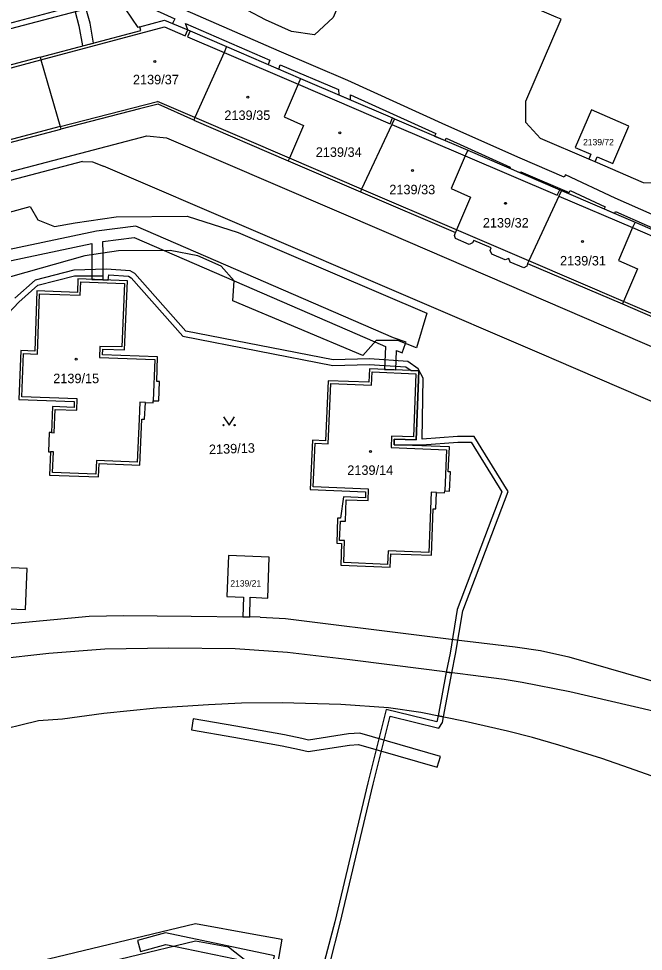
# Model space of a CAD drawing. Extents: x -756746 to -753363, y -1166406 to -1161727.
# Drawn here: x -756319.3 to -756207.5, y -1164267.8 to -1164100.9 of the extents above; entities that cross this region are included whole.
import ezdxf

# ---------------------------------------------------------------- set-up
doc = ezdxf.new("R2010")
doc.units = 0
for name, color, linetype in [('Hranice parcel', 7, 'Continuous'), ('Parcelní čísla', 7, 'Continuous'), ('Vnitřní kresba', 7, 'Continuous'), ('Věcná břemena k části', 7, 'Continuous'), ('Značky budov', 7, 'Continuous'), ('Značky kultur', 7, 'Continuous')]:
    doc.layers.add(name, color=color, linetype=linetype)

msp = doc.modelspace()

# ---------------------------------------------------------------- linework, layer by layer
at = {"layer": 'Hranice parcel'}
for p, q in [((-756315.45, -1164107.81), (-756297.46, -1164103.08)), ((-756297.46, -1164103.08), (-756297.61, -1164102.39)), ((-756282.1, -1164105.94), (-756268.86, -1164111.63)), ((-756287.76, -1164118.62), (-756287.99, -1164119.11)), ((-756287.99, -1164119.11), (-756271.06, -1164126.38)), ((-756252.09, -1164118.84), (-756238.94, -1164124.5)), ((-756271.06, -1164126.38), (-756258.17, -1164131.91)), ((-756216.14, -1164126.58), (-756217.29, -1164126.09)), ((-756257.94, -1164131.42), (-756258.17, -1164131.91)), ((-756258.17, -1164131.91), (-756241.17, -1164139.21)), ((-756222.17, -1164131.71), (-756209, -1164137.37)), ((-756228.04, -1164144.25), (-756228.27, -1164144.74)), ((-756228.27, -1164144.74), (-756211.29, -1164151.98)), ((-756211.29, -1164151.98), (-756198, -1164157.69))]:
    msp.add_line(p, q, dxfattribs=at)
for points in [[(-756223.11, -1164100.67), (-756256.77, -1164086.19), (-756263.02, -1164100.73), (-756266.38, -1164103.84), (-756270.5, -1164103.24), (-756275.14, -1164101.13), (-756278.31, -1164099.51)], [(-756297.61, -1164102.39), (-756297.92, -1164102.53), (-756300.21, -1164099.16), (-756304.16, -1164098.42), (-756363.79, -1164114.05)], [(-756297.61, -1164102.39), (-756293.24, -1164101.21), (-756289.04, -1164102.96), (-756288.64, -1164103.13), (-756282.1, -1164105.94)], [(-756217.29, -1164126.09), (-756225.92, -1164122.38), (-756228.59, -1164119.53), (-756228.58, -1164115.72), (-756222.26, -1164101.04), (-756223.11, -1164100.67)], [(-756282.1, -1164105.94), (-756282.52, -1164107.01), (-756287.76, -1164118.62)], [(-756315.45, -1164107.81), (-756330.14, -1164111.72), (-756330.01, -1164112.2), (-756331.19, -1164112.52), (-756331.31, -1164112.04), (-756353.66, -1164117.9)], [(-756315.45, -1164107.81), (-756315.31, -1164108.3), (-756311.9, -1164120.25), (-756311.76, -1164120.73)], [(-756268.86, -1164111.63), (-756269.29, -1164112.69), (-756271.79, -1164118.53)], [(-756268.86, -1164111.63), (-756252.4, -1164118.71), (-756252.09, -1164118.84)], [(-756287.99, -1164119.11), (-756294.32, -1164116.27), (-756297.69, -1164117.07), (-756311.76, -1164120.73)], [(-756216.14, -1164126.58), (-756215.78, -1164125.69), (-756213.01, -1164126.87), (-756210.12, -1164120.16), (-756216.84, -1164117.28), (-756219.73, -1164124.01), (-756216.92, -1164125.21), (-756217.29, -1164126.09)], [(-756271.79, -1164118.53), (-756268.34, -1164120.05), (-756270.85, -1164125.88), (-756271.06, -1164126.38)], [(-756252.09, -1164118.84), (-756252.52, -1164119.88), (-756257.94, -1164131.42)], [(-756351.41, -1164126.3), (-756341.53, -1164123.74), (-756340.35, -1164128.24), (-756329.27, -1164125.33), (-756311.76, -1164120.73)], [(-756357.48, -1164137.98), (-756334.62, -1164131.93), (-756296.39, -1164121.91), (-756292.85, -1164122.26), (-756253.11, -1164139.34), (-756186.55, -1164167.99), (-756184.92, -1164172.77), (-756175.62, -1164217.3), (-756144.99, -1164245.44)], [(-756238.94, -1164124.5), (-756239.42, -1164125.48), (-756241.91, -1164131.34)], [(-756238.94, -1164124.5), (-756222.48, -1164131.57), (-756222.17, -1164131.71)], [(-756151.7, -1164169.02), (-756152.31, -1164166.49), (-756154.34, -1164160.57), (-756160.31, -1164152.33), (-756162.91, -1164150.21), (-756165.16, -1164148.15), (-756166.9, -1164145.3), (-756166.68, -1164142.43), (-756178.83, -1164137.13), (-756177.37, -1164133.73), (-756187.3, -1164129.49), (-756188.76, -1164132.89), (-756200.84, -1164127.71), (-756203.83, -1164130.35), (-756207.49, -1164130.3), (-756216.14, -1164126.58)], [(-756241.91, -1164131.34), (-756238.45, -1164132.88), (-756240.95, -1164138.71), (-756241.17, -1164139.21)], [(-756222.17, -1164131.71), (-756222.64, -1164132.68), (-756228.04, -1164144.25)], [(-756333.38, -1164138.94), (-756317.27, -1164134.53), (-756315.86, -1164136.94), (-756312.9, -1164138.13), (-756309.19, -1164137.48), (-756301.87, -1164136.4), (-756289.18, -1164136.27), (-756280.04, -1164139.23), (-756246.3, -1164153.62), (-756248.15, -1164159.84), (-756251.44, -1164158.53), (-756255.37, -1164158.5), (-756257.72, -1164161.2), (-756280.98, -1164151.45), (-756280.77, -1164147.87), (-756283.08, -1164145.21), (-756287.27, -1164143.4), (-756292.17, -1164142.41), (-756301.44, -1164142.47), (-756307.47, -1164143.36), (-756320.78, -1164147.12)], [(-756209, -1164137.37), (-756209.47, -1164138.33), (-756211.99, -1164144.23)], [(-756209, -1164137.37), (-756192.55, -1164144.44), (-756192.25, -1164144.57)], [(-756228.27, -1164144.74), (-756228.36, -1164145.23), (-756228.92, -1164145.53), (-756231.39, -1164144.5), (-756231.59, -1164143.85), (-756232.24, -1164144.11), (-756234.66, -1164143.07), (-756234.93, -1164142.4), (-756234.78, -1164141.95), (-756237.89, -1164140.62), (-756238.08, -1164141.06), (-756238.73, -1164141.33), (-756241.13, -1164140.29), (-756241.34, -1164139.76), (-756241.17, -1164139.21)], [(-756211.99, -1164144.23), (-756208.59, -1164145.69), (-756211.1, -1164151.52), (-756211.29, -1164151.98)], [(-756295.23, -1164169.31), (-756294.23, -1164169.34), (-756294.11, -1164165.89), (-756294.61, -1164165.87), (-756294.45, -1164161.46), (-756304.31, -1164161.11), (-756304.27, -1164160.09), (-756300.34, -1164160.2), (-756299.84, -1164147.87), (-756308.69, -1164147.51), (-756308.78, -1164149.92), (-756316.03, -1164149.65), (-756316.44, -1164160.43), (-756318.89, -1164160.33), (-756319.25, -1164169.09), (-756309.35, -1164169.46), (-756309.39, -1164170.49), (-756313.27, -1164170.34), (-756313.45, -1164175.01), (-756313.82, -1164174.99), (-756313.96, -1164178.42), (-756313.59, -1164178.43), (-756313.76, -1164182.64), (-756305, -1164182.94), (-756304.92, -1164180.53), (-756297.62, -1164180.84), (-756297.27, -1164172.6), (-756296.77, -1164172.62), (-756296.64, -1164169.62)], [(-756243.04, -1164185.43), (-756242.24, -1164185.47), (-756242.07, -1164182.02), (-756242.45, -1164182), (-756242.25, -1164177.57), (-756252.15, -1164177.18), (-756252.11, -1164176.15), (-756248.2, -1164176.32), (-756247.69, -1164163.97), (-756256.55, -1164163.6), (-756256.66, -1164166.01), (-756263.95, -1164165.72), (-756264.39, -1164176.48), (-756266.76, -1164176.38), (-756267.13, -1164185.17), (-756257.22, -1164185.61), (-756257.27, -1164186.65), (-756261.17, -1164186.49), (-756261.72, -1164190.32), (-756262.23, -1164190.3), (-756262.4, -1164194.77), (-756261.52, -1164194.82), (-756261.68, -1164198.7), (-756252.83, -1164199.11), (-756252.73, -1164196.71), (-756245.42, -1164196.96), (-756245.14, -1164188.65), (-756244.64, -1164188.66), (-756244.52, -1164185.71)], [(-756296.64, -1164169.62), (-756295.24, -1164169.67), (-756295.23, -1164169.31)], [(-756244.52, -1164185.71), (-756243.1, -1164185.76), (-756243.04, -1164185.43)], [(-756282.07, -1164204.34), (-756279.05, -1164204.45), (-756279.17, -1164207.96), (-756277.94, -1164207.97), (-756277.91, -1164204.42), (-756274.75, -1164204.62), (-756274.46, -1164197.29), (-756281.77, -1164196.99), (-756282.07, -1164204.34)], [(-756321.16, -1164206.56), (-756318.1, -1164206.67), (-756317.78, -1164199.33), (-756325.13, -1164199.01), (-756325.41, -1164206.39), (-756322.39, -1164206.51), (-756322.5, -1164209.38), (-756321.24, -1164209.24), (-756321.16, -1164206.56)], [(-756148.36, -1164249.07), (-756153.72, -1164245.95), (-756161.21, -1164238.9), (-756170.46, -1164234.4), (-756177.88, -1164231.27), (-756185.24, -1164228.27), (-756190.49, -1164227.79), (-756205.8, -1164224.82), (-756220.7, -1164221.36), (-756229.23, -1164219.69), (-756232.44, -1164219.17), (-756246.35, -1164217.38), (-756260.03, -1164215.68), (-756271.23, -1164214.36), (-756280.57, -1164213.67), (-756292.45, -1164213.57), (-756303.87, -1164213.75), (-756313.9, -1164214.51), (-756323.57, -1164215.6), (-756333.21, -1164216.94), (-756339.63, -1164217.97), (-756353.1, -1164221.07)], [(-756205.15, -1164236.76), (-756210, -1164235.05), (-756214.99, -1164233.33), (-756222.65, -1164230.91), (-756227.38, -1164229.56), (-756231.87, -1164228.45), (-756239.41, -1164226.68), (-756247.36, -1164225.07), (-756253.15, -1164224.26), (-756261.68, -1164223.66), (-756272.14, -1164223.37), (-756279.45, -1164223.39), (-756285.31, -1164223.72), (-756294.64, -1164224.32), (-756304.04, -1164225.26), (-756311.44, -1164226.29), (-756315.76, -1164226.6), (-756324.56, -1164228.71)]]:
    msp.add_lwpolyline(points, dxfattribs=at)
at = {"layer": 'Vnitřní kresba'}
for p, q in [((-756315.31, -1164108.3), (-756293.22, -1164102.43)), ((-756293.22, -1164102.43), (-756289.49, -1164104.03)), ((-756289.49, -1164104.03), (-756289.04, -1164102.96)), ((-756288.64, -1164103.13), (-756289.08, -1164104.2)), ((-756289.08, -1164104.2), (-756282.52, -1164107.01)), ((-756282.52, -1164107.01), (-756269.29, -1164112.69)), ((-756329.32, -1164112.02), (-756315.31, -1164108.3)), ((-756269.29, -1164112.69), (-756252.82, -1164119.75)), ((-756311.9, -1164120.25), (-756294.45, -1164115.75)), ((-756287.76, -1164118.62), (-756294.45, -1164115.75)), ((-756270.85, -1164125.88), (-756287.76, -1164118.62)), ((-756252.82, -1164119.75), (-756252.4, -1164118.71)), ((-756311.9, -1164120.25), (-756329.4, -1164124.85)), ((-756252.52, -1164119.88), (-756239.42, -1164125.48)), ((-756307.87, -1164126.5), (-756357.09, -1164139.42)), ((-756307.87, -1164126.5), (-756306.11, -1164126.56)), ((-756257.94, -1164131.42), (-756270.85, -1164125.88)), ((-756239.42, -1164125.48), (-756222.96, -1164132.54)), ((-756306.11, -1164126.56), (-756304.1, -1164127.31)), ((-756224.87, -1164161.33), (-756304.1, -1164127.31)), ((-756240.95, -1164138.71), (-756257.94, -1164131.42)), ((-756222.96, -1164132.54), (-756222.48, -1164131.57)), ((-756222.64, -1164132.68), (-756209.47, -1164138.33)), ((-756228.04, -1164144.25), (-756240.95, -1164138.71)), ((-756209.47, -1164138.33), (-756193, -1164145.4)), ((-756211.1, -1164151.52), (-756228.04, -1164144.25)), ((-756308.3, -1164150.44), (-756308.21, -1164148.03)), ((-756308.21, -1164148.03), (-756300.36, -1164148.35)), ((-756300.36, -1164148.35), (-756300.82, -1164159.68)), ((-756315.96, -1164160.95), (-756315.55, -1164150.17)), ((-756315.55, -1164150.17), (-756308.3, -1164150.44)), ((-756197.8, -1164157.23), (-756211.1, -1164151.52)), ((-756304.76, -1164159.58), (-756304.83, -1164161.59)), ((-756300.82, -1164159.68), (-756304.76, -1164159.58)), ((-756318.73, -1164168.61), (-756318.41, -1164160.85)), ((-756318.41, -1164160.85), (-756315.96, -1164160.95)), ((-756223.49, -1164161.92), (-756224.87, -1164161.33)), ((-756304.83, -1164161.59), (-756294.97, -1164161.94)), ((-756294.97, -1164161.94), (-756295.23, -1164169.31)), ((-756193.75, -1164174.73), (-756223.49, -1164161.92)), ((-756256.18, -1164166.53), (-756256.07, -1164164.12)), ((-756256.07, -1164164.12), (-756248.22, -1164164.46)), ((-756248.22, -1164164.46), (-756248.69, -1164175.79)), ((-756263.91, -1164177), (-756263.47, -1164166.24)), ((-756263.47, -1164166.24), (-756256.18, -1164166.53)), ((-756308.83, -1164168.98), (-756318.73, -1164168.61)), ((-756308.91, -1164171.01), (-756308.83, -1164168.98)), ((-756297.64, -1164169.58), (-756297.77, -1164172.58)), ((-756296.64, -1164169.62), (-756297.64, -1164169.58)), ((-756312.96, -1164175.03), (-756312.79, -1164170.86)), ((-756312.79, -1164170.86), (-756308.91, -1164171.01)), ((-756297.77, -1164172.58), (-756298.1, -1164180.32)), ((-756313.45, -1164175.01), (-756312.96, -1164175.03)), ((-756252.59, -1164175.62), (-756252.68, -1164177.67)), ((-756248.69, -1164175.79), (-756252.59, -1164175.62)), ((-756266.61, -1164184.69), (-756266.28, -1164176.9)), ((-756266.28, -1164176.9), (-756263.91, -1164177)), ((-756252.68, -1164177.67), (-756242.78, -1164178.06)), ((-756242.78, -1164178.06), (-756243.04, -1164185.43)), ((-756313.09, -1164178.45), (-756313.59, -1164178.43)), ((-756313.24, -1164182.16), (-756313.09, -1164178.45)), ((-756305.4, -1164180.01), (-756305.48, -1164182.42)), ((-756298.1, -1164180.32), (-756305.4, -1164180.01)), ((-756305.48, -1164182.42), (-756313.24, -1164182.16)), ((-756256.7, -1164185.13), (-756266.61, -1164184.69)), ((-756256.79, -1164187.17), (-756256.7, -1164185.13)), ((-756245.52, -1164185.67), (-756245.91, -1164196.47)), ((-756244.52, -1164185.71), (-756245.52, -1164185.67)), ((-756260.84, -1164190.87), (-756260.69, -1164187.01)), ((-756260.69, -1164187.01), (-756256.79, -1164187.17)), ((-756261.88, -1164194.29), (-756261.74, -1164190.83)), ((-756261.74, -1164190.83), (-756260.84, -1164190.87)), ((-756260.99, -1164194.33), (-756261.88, -1164194.29)), ((-756261.15, -1164198.22), (-756260.99, -1164194.33)), ((-756253.21, -1164196.18), (-756253.32, -1164198.59)), ((-756245.91, -1164196.47), (-756253.21, -1164196.18)), ((-756253.32, -1164198.59), (-756261.15, -1164198.22)), ((-756321.24, -1164209.24), (-756306.68, -1164207.87)), ((-756306.68, -1164207.87), (-756300.49, -1164207.71)), ((-756300.49, -1164207.71), (-756294.52, -1164207.8)), ((-756294.52, -1164207.8), (-756288.43, -1164207.86)), ((-756288.43, -1164207.86), (-756279.17, -1164207.96)), ((-756276.12, -1164208), (-756277.94, -1164207.97)), ((-756276.12, -1164208), (-756271.59, -1164208.28)), ((-756271.59, -1164208.28), (-756247.63, -1164211.24)), ((-756247.63, -1164211.24), (-756240.02, -1164212.22)), ((-756240.02, -1164212.22), (-756230.45, -1164213.35)), ((-756230.45, -1164213.35), (-756225.95, -1164214.01)), ((-756225.95, -1164214.01), (-756220.88, -1164215.15)), ((-756220.88, -1164215.15), (-756189.12, -1164224.22)), ((-756316.96, -1164269.88), (-756287.66, -1164262.86)), ((-756287.66, -1164262.86), (-756277.2, -1164264.73)), ((-756277.2, -1164264.73), (-756272.2, -1164265.62)), ((-756317.43, -1164273.08), (-756287.67, -1164265.96)), ((-756287.67, -1164265.96), (-756281.76, -1164267.01)), ((-756272.2, -1164265.62), (-756273.02, -1164270.12)), ((-756281.76, -1164267.01), (-756278.66, -1164269.46))]:
    msp.add_line(p, q, dxfattribs=at)
at = {"layer": 'Věcná břemena k části'}
for points in [[(-756300.96, -1164096.54), (-756291.36, -1164100.96), (-756291.77, -1164101.82)], [(-756326.56, -1164103.26), (-756309.49, -1164098.72)], [(-756309.21, -1164099.74), (-756308.54, -1164102.21), (-756307.89, -1164105.82), (-756305.89, -1164105.3), (-756306.52, -1164101.75), (-756307.22, -1164099.22)], [(-756199.32, -1164138.89), (-756212.6, -1164133.03), (-756221.47, -1164128.9), (-756221.72, -1164129.31), (-756229.59, -1164125.91), (-756242.86, -1164119.97), (-756260.4, -1164112), (-756272.67, -1164106.76), (-756289.53, -1164099.42)], [(-756291.77, -1164101.82), (-756289.04, -1164102.96), (-756289.46, -1164101.81), (-756274.39, -1164108.37), (-756274.65, -1164109.14), (-756272.75, -1164109.96), (-756272.49, -1164109.18), (-756262.06, -1164113.64), (-756262.02, -1164114.57), (-756259.92, -1164115.48), (-756259.96, -1164114.58), (-756244.69, -1164121.51), (-756244.89, -1164121.94), (-756242.99, -1164122.76), (-756242.81, -1164122.35), (-756231.35, -1164127.49), (-756231.44, -1164127.72), (-756229.55, -1164128.53), (-756229.47, -1164128.32), (-756220.82, -1164132.05), (-756220.61, -1164131.68), (-756214.38, -1164134.58), (-756214.54, -1164134.99), (-756212.65, -1164135.8), (-756212.5, -1164135.43), (-756201.16, -1164140.44)], [(-756352.82, -1164151.04), (-756306.22, -1164141.16), (-756306.21, -1164143.17), (-756306.19, -1164147.61), (-756304.19, -1164147.69), (-756304.21, -1164142.88), (-756304.22, -1164140.81), (-756298.65, -1164140.09), (-756293.28, -1164142.42), (-756280.77, -1164147.87), (-756255.59, -1164158.75), (-756253.69, -1164159.58), (-756253.83, -1164163.71), (-756251.83, -1164163.8), (-756251.71, -1164160.34), (-756250.67, -1164160.72), (-756250.07, -1164159.08), (-756249.99, -1164158.84), (-756252.26, -1164158.02), (-756298.35, -1164138.04), (-756305.39, -1164138.95), (-756352.3, -1164148.88)], [(-756334.92, -1164168.19), (-756319.27, -1164151.66), (-756315.86, -1164148.62), (-756309.29, -1164146.93), (-756304.45, -1164146.95), (-756304.22, -1164147.04), (-756304.27, -1164147.69), (-756303.27, -1164147.73), (-756303.2, -1164146.78), (-756299.66, -1164147.03), (-756299.15, -1164147.33), (-756289.91, -1164157.78), (-756263.1, -1164163.01), (-756256.57, -1164162.81), (-756250.04, -1164163.25), (-756249.1, -1164163.91), (-756247.69, -1164163.97), (-756248.2, -1164176.32), (-756252.11, -1164176.15), (-756252.15, -1164177.18), (-756247.13, -1164177.2), (-756240.74, -1164176.73), (-756238.34, -1164176.7), (-756232.83, -1164185.63), (-756240.83, -1164206.65), (-756242.11, -1164214.48), (-756242.79, -1164217.84), (-756241.79, -1164217.97), (-756241.13, -1164214.66), (-756239.85, -1164206.91), (-756231.71, -1164185.53), (-756237.78, -1164175.7), (-756240.78, -1164175.73), (-756247.11, -1164176.2), (-756246.96, -1164165.25), (-756247.83, -1164163.58), (-756249.7, -1164162.27), (-756256.55, -1164161.81), (-756263.02, -1164162.01), (-756289.39, -1164156.86), (-756298.51, -1164146.55), (-756299.36, -1164146.05), (-756303.57, -1164145.75), (-756309.41, -1164145.93), (-756316.34, -1164147.72), (-756319.97, -1164150.94)], [(-756263.66, -1164270.03), (-756261.78, -1164262.75), (-756255.87, -1164237.9), (-756252.82, -1164225.75), (-756244.14, -1164227.87), (-756243.48, -1164226.9), (-756243.29, -1164225.89), (-756244.27, -1164225.7), (-756244.47, -1164226.76), (-756253.54, -1164224.55), (-756256.85, -1164237.66), (-756262.76, -1164262.51), (-756264.56, -1164269.51)]]:
    msp.add_lwpolyline(points, dxfattribs=at)
for points in [[(-756244.27, -1164225.7), (-756243.29, -1164225.89), (-756241.79, -1164217.97), (-756242.79, -1164217.84)], [(-756288.06, -1164226.22), (-756288.4, -1164228.2), (-756280.78, -1164229.51), (-756272.13, -1164231.03), (-756269.08, -1164231.7), (-756267.5, -1164232.07), (-756260.1, -1164230.9), (-756258.5, -1164230.8), (-756244.4, -1164234.86), (-756243.84, -1164232.94), (-756258.26, -1164228.78), (-756260.32, -1164228.9), (-756267.42, -1164230.03), (-756268.64, -1164229.74), (-756271.75, -1164229.07), (-756280.44, -1164227.53)], [(-756292.95, -1164266.58), (-756273.95, -1164270.56), (-756273.54, -1164268.6), (-756293.01, -1164264.52), (-756298.03, -1164265.89), (-756297.51, -1164267.82)]]:
    msp.add_lwpolyline(points, close=True, dxfattribs=at)
at = {"layer": 'Značky budov'}
for centre in [(-756294.93, -1164108.6), (-756278.3, -1164114.98), (-756261.86, -1164121.38), (-756248.82, -1164128.13), (-756232.2, -1164133.98), (-756218.44, -1164140.83), (-756309.01, -1164161.89), (-756256.36, -1164178.37)]:
    msp.add_circle(centre, 0.175, dxfattribs=at)
at = {"layer": 'Značky kultur'}
msp.add_lwpolyline([(-756282.66, -1164172.18), (-756281.66, -1164173.68), (-756280.66, -1164172.18)], dxfattribs=at)
for centre in [(-756282.66, -1164173.68), (-756280.66, -1164173.68)]:
    msp.add_circle(centre, 0.1, dxfattribs=at)

# ---------------------------------------------------------------- texts
at = {"layer": 'Parcelní čísla'}
for s, height, p in [('2139/37', 1.7, (-756298.86, -1164112.69)), ('2139/35', 1.7, (-756282.5, -1164119.07)), ('2139/72', 1.139, (-756218.32, -1164123.6)), ('2139/34', 1.7, (-756266.15, -1164125.67)), ('2139/33', 1.7, (-756252.99, -1164132.37)), ('2139/32', 1.7, (-756236.26, -1164138.31)), ('2139/31', 1.7, (-756222.45, -1164145.1)), ('2139/15', 1.7, (-756313.12, -1164166.16)), ('2139/14', 1.7, (-756260.51, -1164182.57)), ('2139/21', 1.139, (-756281.43, -1164202.55))]:
    msp.add_text(s, height=height, dxfattribs=at).set_placement(p)
msp.add_text('2139/13', height=1.7, rotation=2, dxfattribs=at).set_placement((-756285.23, -1164178.87))

doc.saveas('drawing.dxf')
